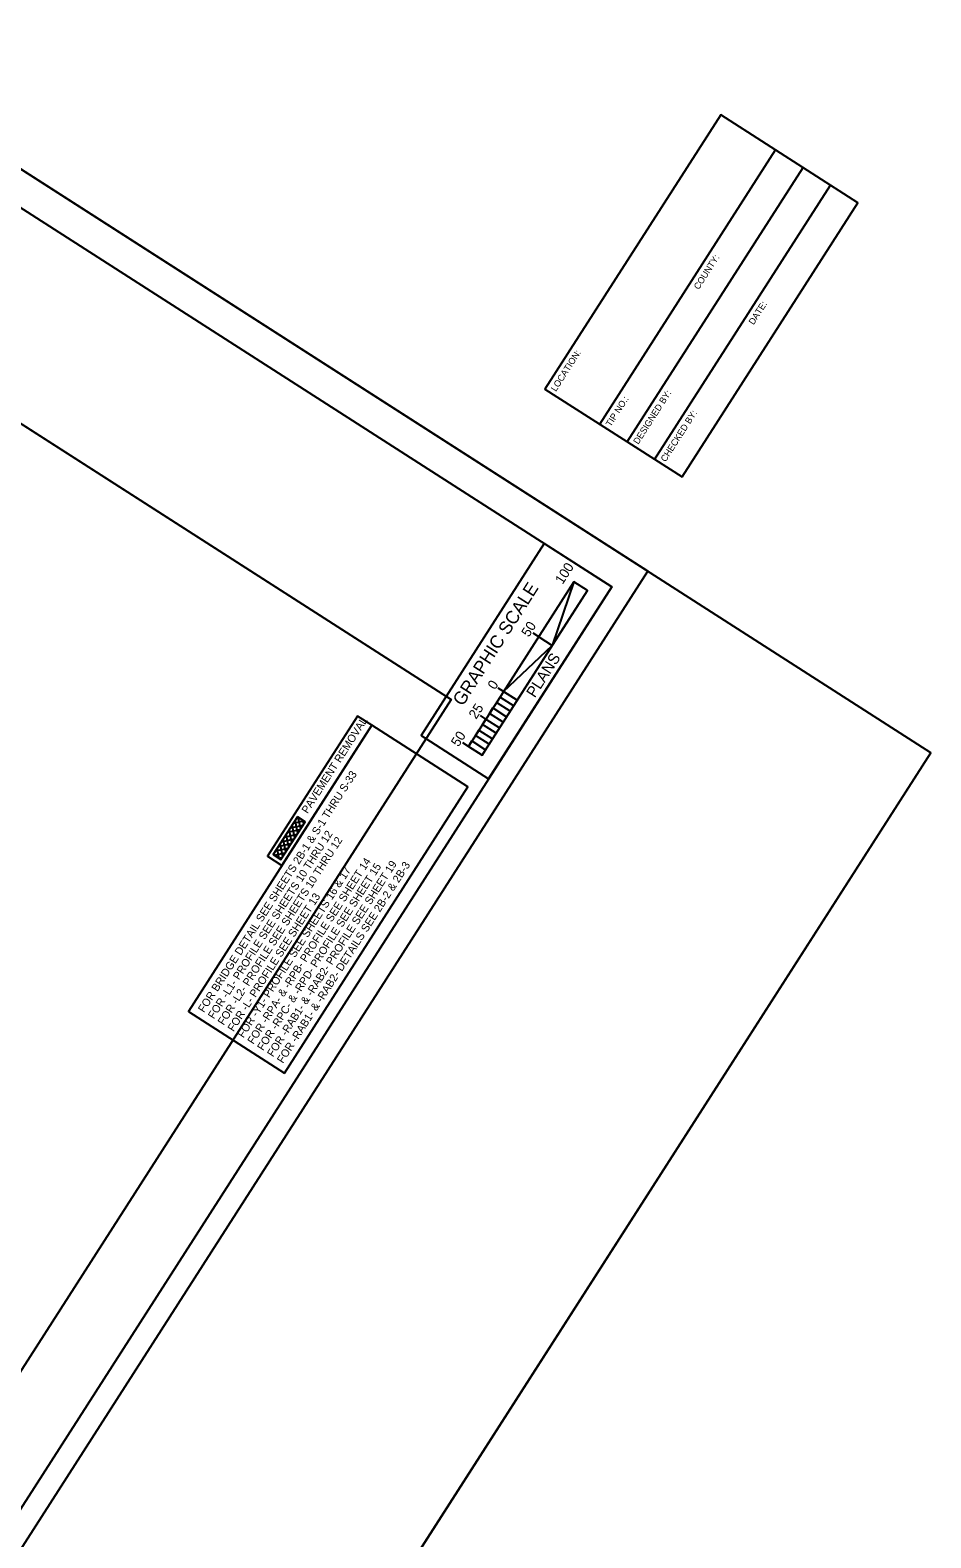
# Model space of a CAD drawing. Extents: x 2346049 to 2349719, y 842061 to 846435.
# Drawn here: x 2349027 to 2349719, y 844432 to 845588 of the extents above; entities that cross this region are included whole.
import ezdxf

# ---------------------------------------------------------------- set-up
doc = ezdxf.new("R2010")
doc.units = 0
for name, color, linetype in [('Default', 7, 'Continuous'), ('Prop DSN Text', 7, 'Continuous'), ('Prop PFL Text', 7, 'Continuous'), ('Scratch_Level_0', 7, 'Continuous'), ('Sheet Cutting Line CELL', 7, 'Continuous'), ('Sheet Detail CELL', 7, 'Continuous'), ('Sheet Plot Border Inside CELL', 7, 'Continuous'), ('Sheet Plot Border Outside CELL', 7, 'Continuous')]:
    doc.layers.add(name, color=color, linetype=linetype)

msp = doc.modelspace()

# ---------------------------------------------------------------- linework, layer by layer
at = {"layer": 'Default'}
for p, q in [((2349227.1, 844976.4), (2349236.9, 844978.5)), ((2349230.5, 844968.6), (2349228.4, 844978.3)), ((2349229.4, 844980), (2349237.2, 844981.7)), ((2349232.8, 844972.2), (2349230.7, 844981.9)), ((2349231.7, 844983.6), (2349233.6, 844984)), ((2349235.1, 844975.7), (2349233.2, 844984.2)), ((2349237.4, 844979.3), (2349236.8, 844981.9)), ((2349220.3, 844965.7), (2349230, 844967.8)), ((2349223.6, 844957.9), (2349221.5, 844967.6)), ((2349222.6, 844969.3), (2349232.3, 844971.4)), ((2349225.9, 844961.5), (2349223.8, 844971.2)), ((2349224.8, 844972.9), (2349234.6, 844975)), ((2349228.2, 844965), (2349226.1, 844974.7)), ((2349215, 844955.1), (2349214.6, 844956.9)), ((2349214.7, 844955.3), (2349223.1, 844957.1)), ((2349215.7, 844958.6), (2349225.4, 844960.7)), ((2349218.5, 844952.8), (2349216.9, 844960.5)), ((2349218, 844962.1), (2349227.7, 844964.3)), ((2349221.3, 844954.3), (2349219.2, 844964)), ((2349218.3, 844953), (2349220.8, 844953.6))]:
    msp.add_line(p, q, dxfattribs=at)
for points in [[(2349220.5, 844947.5), (2349289.6, 845055), (2349278.6, 845062.1), (2349209.5, 844954.5)], [(2349232.5, 844984.7), (2349213.9, 844955.8), (2349219.8, 844952), (2349238.4, 844980.9)]]:
    msp.add_lwpolyline(points, close=True, dxfattribs=at)
at = {"layer": 'Prop PFL Text'}
msp.add_lwpolyline([(2349222.6, 844788.2), (2349363.4, 845007.7), (2349289.6, 845055), (2349148.9, 844835.5)], close=True, dxfattribs=at)
at = {"layer": 'Scratch_Level_0'}
for points in [[(2347005, 844312.5), (2347188.2, 844598.2), (2347979.3, 845831.9), (2348174.5, 845706.7), (2348063.3, 845523.1), (2348169.5, 845452.2), (2348364.5, 845707), (2348364.5, 845707), (2348364.5, 845707), (2349350.4, 845074.8), (2349350.4, 845074.8), (2349350.4, 845074.8), (2348851.8, 844297.2)], [(2347005, 844312.5), (2347188.2, 844598.2), (2347979.3, 845831.9), (2348174.5, 845706.7), (2348235.6, 845791.3), (2348313, 845745.3), (2348364.5, 845707), (2348364.5, 845707), (2348364.5, 845707), (2349350.4, 845074.8), (2349350.4, 845074.8), (2349350.4, 845074.8), (2348851.8, 844297.2)], [(2346937.8, 844263.6), (2347160.2, 844610.4), (2347405.1, 844503.5), (2347561.1, 844746.9), (2347567.3, 844745.9), (2347677, 844903.8), (2347773, 845052.5), (2348231.5, 845792.3), (2348231.5, 845792.3), (2348231.5, 845792.3), (2349350.4, 845074.8), (2349350.4, 845074.8), (2349350.4, 845074.8), (2348851.8, 844297.2)]]:
    msp.add_lwpolyline(points, dxfattribs=at)
at = {"layer": 'Sheet Cutting Line CELL'}
msp.add_line((2347900.5, 842198.8), (2349718.7, 845033.9), dxfattribs=at)
msp.add_line((2347900.5, 842198.8), (2349718.7, 845033.9), dxfattribs=at)
at = {"layer": 'Sheet Detail CELL'}
for p, q in [((2349464.6, 845286), (2349599.5, 845496.5)), ((2349485.6, 845272.5), (2349620.6, 845483)), ((2349506.6, 845259), (2349641.6, 845469.5)), ((2349444.7, 845165.1), (2349363.7, 845038.8)), ((2349374.2, 845032.1), (2349455.1, 845158.4)), ((2349417.7, 845123), (2349413.5, 845125.7)), ((2349417.7, 845123), (2349428.1, 845116.3)), ((2349390.7, 845080.9), (2349386.5, 845083.6)), ((2349390.7, 845080.9), (2349401.2, 845074.2)), ((2349377.2, 845059.8), (2349373, 845062.5)), ((2349363.7, 845038.8), (2349359.5, 845041.5)), ((2349363.7, 845038.8), (2349374.2, 845032.1))]:
    msp.add_line(p, q, dxfattribs=at)
for points in [[(2346465.3, 843526.7), (2348084.7, 846052), (2349473.7, 845161.3), (2347854.2, 842636)], [(2349527.7, 845245.6), (2349662.6, 845456), (2349557.4, 845523.5), (2349422.5, 845313)], [(2349379.2, 845014), (2349473.7, 845161.3), (2349422, 845194.5), (2349327.5, 845047.2)], [(2349444.7, 845165.1), (2349428.1, 845116.3), (2349455.1, 845158.4)], [(2349390.7, 845080.9), (2349428.1, 845116.3), (2349401.2, 845074.2)], [(2349385.3, 845072.5), (2349388, 845076.7), (2349398.5, 845070), (2349395.8, 845065.8)], [(2349390.7, 845080.9), (2349401.2, 845074.2)], [(2349374.5, 845055.6), (2349377.2, 845059.8), (2349387.7, 845053.1), (2349385, 845048.9)], [(2349379.9, 845064), (2349382.6, 845068.3), (2349393.1, 845061.6), (2349390.4, 845057.4)], [(2349369.1, 845047.2), (2349371.8, 845051.4), (2349382.3, 845044.7), (2349379.6, 845040.5)], [(2349363.7, 845038.8), (2349366.4, 845043), (2349376.9, 845036.3), (2349374.2, 845032.1)]]:
    msp.add_lwpolyline(points, close=True, dxfattribs=at)
at = {"layer": 'Sheet Plot Border Inside CELL'}
msp.add_lwpolyline([(2348083.9, 846082.3), (2346302.5, 843304.4), (2347720, 842395.3), (2349501.5, 845173.2)], close=True, dxfattribs=at)
at = {"layer": 'Sheet Plot Border Outside CELL'}
msp.add_lwpolyline([(2347866.8, 846221.5), (2346048.7, 843386.4), (2347900.5, 842198.8), (2349718.7, 845033.9)], close=True, dxfattribs=at)

# ---------------------------------------------------------------- texts
at = {"layer": 'Prop DSN Text'}
for s, rotation, p in [('PAVEMENT REMOVAL', 57.2702, (2349240.3, 844986.8)), ('FOR BRIDGE DETAIL SEE SHEETS 2B-1 & S-1 THRU S-33', 57.3281, (2349160.8, 844834.1)), ('FOR -L1- PROFILE SEE SHEETS 10 THRU 12', 57.3281, (2349168.4, 844829.2)), ('FOR -L2- PROFILE SEE SHEETS 10 THRU 12', 57.3281, (2349175.9, 844824.4)), ('FOR -Y1- PROFILE SEE SHEETS 16 & 17', 57.3281, (2349191.1, 844814.7)), ('FOR -RPA- & -RPB- PROFILE SEE SHEET 14', 57.3281, (2349198.7, 844809.8)), ('FOR -RPC- & -RPD- PROFILE SEE SHEET 15', 57.3281, (2349206.2, 844804.9)), ('FOR -RAB1- & -RAB2- PROFILE SEE SHEET 19', 57.3281, (2349213.8, 844800.1)), ('FOR -RAB1- & -RAB2- DETAILS SEE 2B-2 & 2B-3', 57.3281, (2349221.4, 844795.2)), ('FOR -L- PROFILE SEE SHEET 13', 57.3281, (2349183.5, 844819.5))]:
    msp.add_text(s, height=6, rotation=rotation, dxfattribs=at).set_placement(p)
at = {"layer": 'Sheet Detail CELL'}
for s, height, p in [('COUNTY:', 5, (2349540.5, 845388.9)), ('DATE:', 5, (2349582.6, 845361.9)), ('LOCATION:', 5, (2349430.9, 845310.7)), ('TIP NO.:', 5, (2349473, 845283.7)), ('DESIGNED BY:', 5, (2349494.1, 845270.2)), ('CHECKED BY:', 5, (2349515.1, 845256.7)), ('100', 7.5, (2349436, 845162.6)), ('GRAPHIC SCALE', 10, (2349359.4, 845069.1)), ('50', 7.5, (2349410.1, 845122.2)), ('PLANS', 8.5, (2349414.7, 845075.6)), ('0', 7.5, (2349384.2, 845081.8)), ('25', 7.5, (2349369.7, 845059.2)), ('50', 7.5, (2349356.1, 845038))]:
    msp.add_text(s, height=height, rotation=57.3281, dxfattribs=at).set_placement(p)

doc.saveas('drawing.dxf')
